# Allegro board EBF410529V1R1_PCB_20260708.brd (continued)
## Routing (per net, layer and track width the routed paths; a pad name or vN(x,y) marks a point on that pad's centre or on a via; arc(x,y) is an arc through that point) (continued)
USB3_OTG1_SSTXP: length 60.5
  TOP w0.135: J3.218 70.69,62.6 70.6,62.51 70.6,61.18 arc(70.63,61) 70.73,60.85 71.66,59.92 arc(71.82,59.81) 72.02,59.77 90.74,59.77 arc(91.65,59.95) 92.42,60.47 94.73,62.77 arc(94.84,62.95) 94.89,63.16 94.89,63.7 arc(95.03,64.4) 95.42,64.99 95.81,65.38 arc(96.68,65.96) 97.71,66.17 108.63,66.17 arc(108.81,66.2) 108.97,66.31 109.8,67.14 arc(109.91,67.3) 109.95,67.49 109.95,67.56 arc(109.92,67.72) 109.83,67.85 v1(109.69,67.99) ; v1(119.33,67.18) 119.19,67.32 arc(119.1,67.45) 119.07,67.61 119.07,67.75 arc(119.11,67.96) 119.23,68.15 C98.2
  ART03 w0.135: v1(109.69,67.99) 109.83,67.85 arc(109.92,67.72) 109.95,67.56 109.95,67.24 arc(110.41,66.14) 111.52,65.68 118.18,65.68 arc(118.81,65.94) 119.07,66.57 119.07,66.74 arc(119.1,66.9) 119.19,67.04 v1(119.33,67.18)
USB20_DM2: length 9.2
  TOP w0.135: J11.11 115.43,76.92 arc(115.35,76.73) 115.43,76.54 115.64,76.34 arc(115.75,76.17) 115.79,75.98 115.79,75.47 arc(115.85,75.12) 116.05,74.83 116.26,74.62 arc(116.38,74.57) 116.5,74.62 arc(116.62,74.67) 116.75,74.62 116.98,74.38 arc(117.03,74.26) 116.98,74.14 arc(116.93,74.02) 116.98,73.9 117.26,73.62 117.26,73.1 117.36,73 U15.9 U15.2 117.36,71.01 117.26,70.92 117.26,69.63 arc(117.29,69.47) R115.1
USB20_DP2: length 9.7
  TOP w0.135: R116.1 116.84,69.8 arc(116.88,69.85) 116.91,69.9 arc(116.94,69.99) 116.95,70.08 116.95,70.92 116.86,71.01 U15.1 U15.10 116.86,73 116.95,73.1 116.95,73.49 115.83,74.61 arc(115.57,75) 115.47,75.47 115.47,75.91 arc(115.45,76.04) 115.37,76.16 114.81,76.72 arc(114.3,77.06) J11.12
USB20_HOST_PWR_EN: length 103
  TOP w0.107: J3.224 72.19,66.19 71.12,67.26 71.12,72.86 v1(71.99,73.74) ; v1(138.81,85.79) 136.41,88.19 108.66,88.19 105.23,84.76 105.23,70.28 103,68.05 96.06,68.05 94.8,66.8 92.33,66.8 91.19,65.66 82.35,65.66 81.66,66.34 81.66,67.61 80.7,68.58 75.41,68.58 74.22,69.77 74.22,73.04 v1(73.52,73.74)
  BOTTOM w0.107: v1(71.99,73.74) v1(73.52,73.74) ; R134.1 v1(138.81,85.79)
USB30_DM: length 13.2
  BOTTOM w0.135: R105.1 116.8,69.76 arc(116.68,69.93) 116.64,70.13 116.64,70.37 arc(116.61,70.56) 116.5,70.71 116.35,70.87 116.35,71.17 116.44,71.27 U17.6 U17.5 116.44,73.26 116.35,73.35 116.35,73.8 116.53,73.99 arc(116.64,74.03) 116.74,73.99 arc(116.84,73.95) 116.94,73.99 117.12,74.17 arc(117.16,74.27) 117.12,74.37 arc(117.08,74.47) 117.12,74.57 117.3,74.75 arc(117.4,74.79) 117.5,74.75 arc(117.6,74.71) 117.7,74.75 117.88,74.93 arc(117.92,75.03) 117.88,75.13 117.85,75.16 arc(117.82,75.23) 117.85,75.3 117.92,75.37 117.92,75.84 arc(117.84,76.24) 117.61,76.58 117.15,77.04 117.15,77.25 116.04,78.37 arc(115.87,78.61) 115.81,78.91 115.81,80.09 arc(115.78,80.25) J11.2
USB30_DP: length 13.7
  BOTTOM w0.135: R106.1 116.17,69.81 arc(116.29,69.99) 116.33,70.19 116.33,70.37 arc(116.32,70.44) 116.28,70.49 116.04,70.74 116.04,71.17 115.94,71.27 U17.7 U17.4 115.94,73.26 116.04,73.35 116.04,73.93 117.61,75.5 117.61,75.84 arc(117.55,76.12) 117.39,76.36 116.84,76.91 116.84,77.12 115.81,78.15 arc(115.58,78.5) 115.5,78.91 115.5,78.93 arc(115.46,79.21) 115.35,79.48 arc(115.27,79.58) 115.19,79.68 114.6,80.27 arc(114.47,80.35) 114.33,80.38 J11.3
USB30_HOST_PWR_EN: length 81.3
  TOP w0.107: v1(73.52,72.74) 73.94,72.32 73.94,69.55 75.29,68.2 80.57,68.2 81.4,67.37 81.4,66.09 82.12,65.37 91.26,65.37 92.44,66.54 94.91,66.54 96.13,67.76 103.32,67.76 105.53,69.97 105.53,84.57 108.71,87.76 v1(119.49,87.76) ; v1(71.99,72.74) 71.53,72.27 71.53,67.46 72.69,66.3 J3.226
  BOTTOM w0.107: v1(71.99,72.74) v1(73.52,72.74) ; R121.1 v1(119.49,87.76)
USB30_RXN: length 12.8
  BOTTOM w0.135: J11.5 111.09,78.88 arc(111.25,78.85) 111.39,78.76 111.41,78.74 arc(111.5,78.6) 111.53,78.43 111.53,78.35 arc(111.58,78.12) 111.71,77.93 112.17,77.47 arc(112.28,77.19) 112.17,76.92 111.86,76.62 arc(111.65,76.3) 111.57,75.92 111.57,75.59 arc(111.66,75.15) 111.91,74.78 111.93,74.76 arc(112.3,74.51) 112.74,74.42 113.62,74.42 arc(113.83,74.38) 114,74.26 114.42,73.85 arc(114.51,73.72) 114.54,73.56 114.54,73.35 114.44,73.26 U17.1 U17.10 114.44,71.27 114.54,71.17 114.54,70.79 114.3,70.56 114.3,70.23 arc(114.28,70.08) 114.22,69.94 arc(114.17,69.85) 114.09,69.76 R110.1
USB30_RXP: length 12.7
  BOTTOM w0.135: R111.1 114.76,69.76 arc(114.65,69.93) 114.61,70.13 114.61,70.43 114.85,70.66 114.85,71.17 114.94,71.27 U17.9 U17.2 114.94,73.26 114.85,73.35 114.85,73.56 arc(114.79,73.83) 114.64,74.07 114.22,74.49 arc(113.95,74.67) 113.62,74.73 112.74,74.73 arc(112.42,74.8) 112.15,74.98 112.13,75 arc(111.95,75.27) 111.89,75.59 111.89,75.92 arc(111.94,76.18) 112.09,76.4 112.39,76.7 arc(112.59,77.19) 112.39,77.69 111.93,78.15 arc(111.87,78.24) 111.85,78.35 111.85,78.43 arc(111.88,78.6) 111.97,78.74 111.99,78.76 arc(112.13,78.85) 112.29,78.88 J11.6
USB30_TXN: length 11.2
  TOP w0.135: C97.1 118.65,69.58 arc(118.74,69.72) 118.77,69.88 118.77,70.09 118.61,70.25 arc(118.49,70.43) 118.45,70.63 118.45,70.92 118.36,71.01 U15.4 U15.7 118.36,73 118.45,73.1 118.45,73.39 arc(118.4,73.62) 118.27,73.82 117.95,74.14 arc(117.63,74.62) 117.52,75.18 117.52,75.72 arc(117.43,76.17) 117.18,76.55 117.13,76.59 arc(116.88,77.2) 117.13,77.82 117.4,78.08 arc(117.5,78.23) 117.53,78.4 117.53,78.43 arc(117.5,78.6) 117.41,78.74 117.39,78.76 arc(117.25,78.85) 117.09,78.88 J11.8
USB30_TXP: length 11.2
  TOP w0.135: J11.9 118.29,78.88 arc(118.13,78.85) 117.99,78.76 117.97,78.74 arc(117.88,78.6) 117.84,78.43 117.84,78.4 arc(117.79,78.11) 117.62,77.86 117.36,77.59 arc(117.19,77.2) 117.36,76.81 117.4,76.77 arc(117.72,76.29) 117.83,75.72 117.83,75.18 arc(117.92,74.74) 118.17,74.36 118.49,74.04 arc(118.69,73.74) 118.76,73.39 118.76,73.1 118.86,73 U15.6 U15.5 118.86,71.01 118.76,70.92 118.76,70.63 arc(118.78,70.55) 118.83,70.47 119.09,70.22 119.09,69.89 arc(119.13,69.68) 119.24,69.51 C98.1
USB_HUB_1V8: length 29.8
  TOP w0.254: U19.6 111.58,41.33 111.94,40.97 111.94,39.63 C126.1 v1(112.53,38.38) ; C124.1 v1(98.56,42.09) 99.31,42.83 U19.28 ; v1(102.23,50.6) C127.1 103.23,48.7 C123.1 103.25,48.31 104.08,47.48 U19.21 ; C125.1 v1(98.56,45.14) 99.37,44.33 U19.25
  ART03 w0.254: v1(98.56,45.14) 100.1,45.14 101.45,46.48 101.45,49.83 v1(102.23,50.6)
  BOTTOM w0.254: v1(98.56,45.14) 98.17,45.14 97.66,44.63 97.66,42.99 v1(98.56,42.09)
USB_HUB_3V3: length 63.1
  TOP w0.254: C110.1 v1(98.56,44.12) 98.85,43.83 U19.26 ; U19.43 105.58,36.14 C121.1 ; C116.1 v1(104.27,48.03) 104.58,47.71 U19.20 ; C121.1 C117.1 107.44,35.71 106.58,36.57 U19.45 ; C121.1 106.41,35.3 R130.2 105.41,33.45 105.08,33.13 103.91,33.13 103.38,33.66 R129.2 103.36,34.3 C120.1 102.36,35.31 102.11,35.56 102.11,38.48 101.77,38.82 101.09,38.82 U19.36 v1(100.08,38.83) ; U19.15 v1(107.08,44.83) ; U19.31 v1(102.05,41.33) ; R128.2 v1(114.24,45.14)
  TOP w0.381: C117.1 R127.2
  ART03 w0.254: v1(114.24,45.14) 114.24,47.13 112.88,48.49 109.75,48.49 108.76,47.5 108.76,45.21 108.38,44.83 v1(107.08,44.83)
  BOTTOM w0.254: 100.84,44.12 101.19,44.48 101.19,45.24 101.55,45.59 C118.1 ; 100.84,44.12 101.21,43.75 C109.1 ; 100.84,44.12 v1(98.56,44.12) ; C109.1 101.93,41.27 101.98,41.33 v1(102.05,41.33) ; C109.1 101.21,39.97 v1(100.08,38.83) ; C118.1 107.54,46.07 107.54,47.22 106.73,48.03 v1(104.27,48.03) ; C118.1 107.07,44.85 v1(107.08,44.83)
USB_HUB_3V3_OUT: length 5.1
  TOP w0.254: R128.1 C114.1 C115.1 112.26,42.83 U19.9
USB_HUB_5V0: length 5.1
  TOP w0.254: R126.2 C112.1 C113.1 112.29,42.33 U19.8
USB_HUB_DM1: length 32.6
  TOP w0.135: U19.18 105.58,46.63 105.49,46.72 105.49,47.81 arc(105.66,48.67) 106.16,49.41 107.26,50.52 arc(108.03,51.03) 108.95,51.22 113.35,51.22 arc(114.07,51.36) 114.68,51.77 117.32,54.41 arc(117.82,55.15) 117.99,56.02 117.99,64.26 arc(117.92,64.59) 117.74,64.87 116.6,66.01 arc(116.53,66.11) 116.51,66.23 116.51,66.29 arc(116.62,66.56) v1(116.88,66.67)
  BOTTOM w0.135: R105.2 116.78,68.4 arc(116.66,68.22) 116.62,68 116.62,67.88 arc(116.66,67.78) 116.75,67.74 116.75,67.74 arc(116.85,67.7) 116.89,67.6 116.89,67.34 arc(116.85,67.24) 116.75,67.2 116.75,67.2 arc(116.66,67.16) 116.62,67.06 116.62,66.8 arc(116.65,66.71) 116.75,66.67 v1(116.88,66.67)
USB_HUB_DM2: length 32.4
  TOP w0.135: U19.16 106.58,46.63 106.49,46.72 106.49,47.5 arc(106.63,48.18) 107.02,48.76 108.1,49.85 arc(108.62,50.2) 109.23,50.32 113.6,50.32 arc(114.63,50.52) 115.5,51.11 118.29,53.89 arc(118.87,54.76) 119.08,55.79 119.08,62.34 arc(119.11,62.42) 119.19,62.45 arc(119.27,62.49) 119.3,62.57 119.3,63.01 arc(119.27,63.09) 119.19,63.13 arc(119.11,63.16) 119.08,63.24 119.08,63.69 arc(119.11,63.77) 119.19,63.8 arc(119.27,63.83) 119.3,63.91 119.3,64.36 arc(119.27,64.44) 119.19,64.47 arc(119.11,64.51) 119.08,64.59 119.08,64.95 arc(118.96,65.52) 118.64,66 117.1,67.55 arc(117.04,67.63) 117.02,67.73 117.02,67.79 arc(117.05,67.95) 117.14,68.09 R115.2
USB_HUB_DM3: length 48.6
  TOP w0.135: U19.13 108.08,46.63 107.99,46.72 107.99,46.95 arc(108.01,47.02) 108.05,47.09 108.65,47.69 arc(109.03,47.94) 109.47,48.03 115.01,48.03 arc(115.9,48.21) 116.66,48.72 120.89,52.95 arc(121.21,53.42) 121.32,53.98 121.32,60.77 arc(121.5,61.68) 122.01,62.45 124.85,65.28 arc(125.62,65.8) 126.53,65.98 131.8,65.98 arc(132.15,66.05) 132.44,66.24 134.13,67.94 arc(134.33,68.23) 134.39,68.57 134.39,70.92 134.49,71.01 U18.2 U18.9 134.49,73 134.39,73.1 134.39,73.49 arc(134.35,73.73) 134.21,73.93 134.19,73.95 arc(134.06,74.15) 134.01,74.38 134.01,74.41 arc(134.06,74.64) 134.19,74.83 J12.2
USB_HUB_DM4: length 54.2
  TOP w0.135: U19.11 110.25,43.83 110.33,43.91 110.62,43.91 110.82,44.11 arc(110.95,44.31) 111,44.54 111,46.07 arc(111.04,46.29) 111.16,46.47 111.19,46.49 arc(111.37,46.62) 111.59,46.66 114.92,46.66 arc(115.95,46.86) 116.83,47.45 121.94,52.56 arc(122.38,53.22) 122.53,53.99 122.53,60.26 arc(122.67,60.97) 123.07,61.56 126.09,64.59 arc(126.28,64.72) 126.51,64.76 131.55,64.76 arc(132.58,64.97) 133.46,65.55 135.11,67.2 arc(135.69,68.07) 135.89,69.11 135.89,70.92 135.99,71.01 U18.5 U18.6 135.99,73 135.89,73.1 135.89,74.45 136.08,74.64 arc(136.21,74.83) 136.26,75.06 136.26,76.08 arc(136.19,76.43) 135.99,76.72 135.97,76.74 arc(135.68,76.94) 135.33,77.01 134.46,77.01 arc(134.29,77.04) 134.16,77.13 134.14,77.15 arc(134.04,77.29) 134.01,77.45 134.01,77.48 arc(134.02,77.55) 134.04,77.63 arc(134.07,77.69) 134.1,77.74 arc(134.12,77.76) 134.14,77.78 J12.8
USB_HUB_DM5: length 46.6
  TOP w0.135: U19.32 100.39,40.83 100.3,40.74 100.05,40.74 arc(99.4,40.47) 99.13,39.82 99.13,35.89 arc(99.23,35.37) 99.53,34.93 108.29,26.16 arc(109.09,25.63) 110.03,25.44 121.12,25.44 arc(121.46,25.51) 121.75,25.71 121.96,25.91 arc(122.15,26.04) 122.37,26.08 130.64,26.08 arc(130.86,26.04) 131.05,25.91 131.71,25.26 arc(131.83,25.07) 131.87,24.85 131.87,24.73 arc(131.83,24.51) 131.7,24.32 D33.1 131.77,23.87 arc(131.85,23.76) 131.87,23.63 131.87,23.6 arc(131.85,23.48) 131.77,23.37 R184.2
USB_HUB_DM6: length 23.7
  TOP w0.135: U19.34 101.88,39.83 101.97,39.74 103.91,39.74 arc(104.28,39.66) 104.59,39.46 104.7,39.35 arc(104.9,39.21) 105.13,39.17 106.86,39.17 arc(107.89,38.96) 108.76,38.38 109.86,37.28 arc(110.05,37.15) 110.27,37.11 114.21,37.11 arc(114.53,37.05) 114.8,36.87 115.42,36.25 arc(115.59,36.14) 115.78,36.1 122.41,36.1 arc(122.63,36.14) 122.81,36.26 122.85,36.3 arc(123.01,36.41) 123.21,36.45 R143.1
USB_HUB_DP1: length 32
  TOP w0.135: U19.19 105.08,46.63 105.18,46.72 105.18,47.81 arc(105.37,48.79) 105.93,49.63 107.04,50.74 arc(107.91,51.32) 108.95,51.53 113.35,51.53 arc(113.95,51.65) 114.46,51.99 117.1,54.63 arc(117.53,55.27) 117.68,56.02 117.68,64.26 arc(117.64,64.47) 117.52,64.65 116.38,65.79 arc(116.24,65.99) 116.19,66.23 116.19,66.42 arc(116.18,66.5) 116.13,66.58 v1(116.04,66.67)
  BOTTOM w0.135: v1(116.04,66.67) 116.18,66.81 arc(116.27,66.94) 116.3,67.1 116.3,68.07 arc(116.27,68.22) 116.19,68.35 R106.2
USB_HUB_DP2: length 31.9
  TOP w0.135: R116.2 116.55,68.16 arc(116.67,67.98) 116.71,67.77 116.71,67.73 arc(116.75,67.51) 116.88,67.32 118.42,65.78 arc(118.67,65.4) 118.76,64.95 118.76,55.79 arc(118.58,54.88) 118.07,54.11 115.28,51.33 arc(114.51,50.81) 113.6,50.63 109.23,50.63 arc(108.5,50.49) 107.88,50.07 106.79,48.98 arc(106.34,48.3) 106.18,47.5 106.18,46.72 106.08,46.63 U19.17
USB_HUB_DP3: length 48.6
  TOP w0.135: J12.3 133.58,74.77 arc(133.67,74.64) 133.7,74.49 133.7,74.26 arc(133.75,74.02) 133.88,73.82 133.91,73.79 arc(134.04,73.6) 134.08,73.37 134.08,73.1 133.99,73 U18.10 U18.1 133.99,71.01 134.08,70.92 134.08,68.57 arc(134.04,68.35) 133.91,68.16 132.22,66.46 arc(132.03,66.34) 131.8,66.29 126.53,66.29 arc(125.5,66.09) 124.63,65.51 121.79,62.67 arc(121.21,61.8) 121.01,60.77 121.01,53.98 arc(120.92,53.54) 120.67,53.17 116.44,48.94 arc(115.78,48.5) 115.01,48.34 109.47,48.34 arc(108.91,48.23) 108.43,47.91 107.83,47.31 arc(107.72,47.14) 107.68,46.95 107.68,46.72 107.58,46.63 U19.14
USB_HUB_DP4: length 54.2
  TOP w0.135: J12.9 133.05,78.5 arc(133.42,78.39) 133.66,78.1 arc(133.69,78) 133.7,77.9 133.7,77.39 arc(133.74,77.16) 133.87,76.97 133.93,76.91 arc(134.17,76.75) 134.46,76.69 135.33,76.69 arc(135.56,76.65) 135.75,76.52 135.77,76.5 arc(135.9,76.31) 135.95,76.08 135.95,75.06 arc(135.92,74.95) 135.86,74.86 135.58,74.58 135.58,74.32 arc(135.55,74.24) 135.47,74.2 arc(135.39,74.17) 135.36,74.09 135.36,73.78 arc(135.39,73.7) 135.47,73.67 arc(135.55,73.63) 135.58,73.55 135.58,73.1 135.49,73 U18.7 U18.4 135.49,71.01 135.58,70.92 135.58,69.11 arc(135.4,68.19) 134.88,67.42 133.23,65.77 arc(132.46,65.26) 131.55,65.07 126.51,65.07 arc(126.16,65.01) 125.87,64.81 122.85,61.79 arc(122.38,61.09) 122.22,60.26 122.22,53.99 arc(122.09,53.34) 121.72,52.78 116.6,47.67 arc(115.83,47.15) 114.92,46.97 111.59,46.97 arc(111.25,46.91) 110.97,46.71 110.94,46.69 arc(110.75,46.41) 110.69,46.07 110.69,44.54 arc(110.66,44.43) 110.6,44.33 110.49,44.22 110.4,44.22 arc(110.34,44.23) 110.29,44.27 110.27,44.29 arc(110.22,44.32) 110.17,44.33 U19.12
USB_HUB_DP5: length 46.7
  TOP w0.135: R185.2 132.28,23.37 arc(132.21,23.48) 132.19,23.6 132.19,23.63 arc(132.21,23.76) 132.28,23.87 D32.1 132.36,24.32 arc(132.23,24.51) 132.19,24.73 132.19,24.85 arc(132.12,25.19) 131.93,25.48 131.27,26.13 arc(130.98,26.32) 130.64,26.39 122.37,26.39 arc(122.03,26.32) 121.74,26.13 121.53,25.93 arc(121.34,25.8) 121.12,25.76 110.03,25.76 arc(109.21,25.92) 108.51,26.38 99.75,35.15 arc(99.52,35.49) 99.44,35.89 99.44,36.46 arc(99.48,36.55) 99.57,36.59 arc(99.66,36.62) 99.69,36.71 99.69,37 arc(99.66,37.09) 99.57,37.12 arc(99.48,37.16) 99.44,37.25 99.44,37.54 arc(99.48,37.62) 99.57,37.66 arc(99.66,37.7) 99.69,37.79 99.69,38.07 arc(99.66,38.16) 99.57,38.2 arc(99.48,38.24) 99.44,38.33 99.44,39.82 arc(99.62,40.25) 100.05,40.42 100.29,40.42 100.39,40.33 U19.33
USB_HUB_DP6: length 23.7
  TOP w0.135: R138.1 123.21,35.43 arc(123.01,35.47) 122.85,35.58 122.81,35.62 arc(122.63,35.74) 122.41,35.78 115.78,35.78 arc(115.47,35.85) 115.2,36.03 114.58,36.65 arc(114.41,36.76) 114.21,36.8 110.27,36.8 arc(109.93,36.87) 109.64,37.06 108.54,38.16 arc(107.77,38.67) 106.86,38.85 105.13,38.85 arc(104.78,38.92) 104.48,39.12 104.36,39.24 arc(104.16,39.38) 103.91,39.42 101.97,39.42 101.88,39.33 U19.35
WIFI_PWR_EN: length 95.3
  TOP w0.107: R155.1 115.24,39.93 115.24,41.55 v1(115.67,41.99) ; J3.170 58.69,62.44 v1(58.69,62.44)
  BOTTOM w0.107: v1(58.69,62.44) 58.6,62.44 57.76,61.59 57.76,36.73 60.84,33.65 70.05,33.65 70.89,34.49 75.56,34.49 76.12,33.93 77.95,33.93 78.25,33.64 86.29,33.64 87.1,34.44 105.82,34.44 109.88,38.51 109.88,40.31 111.15,41.58 114.94,41.58 115.34,41.99 v1(115.67,41.99)
N16958730: length 10.8
  BOTTOM w0.6: J1.1 10.68,88.09 14.33,88.09 L2.1 J1.5
N16959452: length 3.4
  TOP w0.203: R3.2 8.68,66.67 8.89,66.46 v1(8.89,65.28)
  BOTTOM w0.203: U1.5 v1(8.89,65.28)
N16959497: length 1.3
  BOTTOM w0.381: U1.6 7.86,64.13 C1.1
N16959529: length 3.9
  BOTTOM w0.254: R1.1 C2.1 R2.1 U1.4
N16961195: length 4
  BOTTOM w0.254: C11.1 R6.1 R7.1 16.38,66.23 U2.4
N16961199: length 1.3
  BOTTOM w0.381: C10.1 15.42,63.32 U2.6
N16961300: length 3.8
  BOTTOM w0.381: R9.1 R8.1 14.34,66.02 15.09,65.28 U2.5
N16963036: length 1.5
  TOP w0.107: LED1.2 v1(136.25,2.26)
  BOTTOM w0.107: v1(136.25,2.26) 136.27,2.29 R4.2
N16963423: length 1.5
  TOP w0.107: LED2.2 v1(140.06,2.26)
  BOTTOM w0.107: v1(140.06,2.26) 140.08,2.29 R12.2
N16965184: length 5.6
  BOTTOM w0.132: J4.1 132.68,15.21 D8.2 131.94,14.48 130.55,14.48 R17.2
N16965201: length 5.5
  BOTTOM w0.132: R18.2 130.43,15.74 132.06,15.74 D7.2 132.63,16.31 J4.2
N16965205: length 5.6
  BOTTOM w0.132: J4.3 132.59,17.41 D6.2 131.97,16.79 130.52,16.79 R19.2
N16965209: length 6.6
  BOTTOM w0.132: R20.2 129.91,20.31 130.23,20.63 132.28,20.63 132.58,20.33 D5.2 132.66,19.61 J4.5
N16965213: length 5.5
  BOTTOM w0.132: J4.7 132.67,21.81 D4.2 132.06,21.2 130.43,21.2 R23.2
N16965217: length 5.5
  BOTTOM w0.132: J4.8 132.63,22.91 D3.2 132.06,22.34 130.43,22.34 R24.2
N16965221: length 5.5
  BOTTOM w0.132: R25.2 130.58,24 131.09,23.48 132.06,23.48 D2.2 134.98,24 J4.9
N16966392: length 1.9
  TOP w0.107: U4.3 139.48,7.09 R26.2
N16966399: length 4.2
  TOP w0.107: U4.2 138.21,7.09 C23.1 138.17,7.11 C22.1 R22.2
N16970771: length 4.9
  TOP w0.132: R39.2 63.15,25.1 63.88,25.1 65.17,26.38 U7.23
N16970773: length 4.4
  TOP w0.132: R36.2 63.79,24.71 64.14,24.71 65.57,26.15 U7.24
N16970775: length 4
  TOP w0.132: U7.25 65.97,25.88 R37.2
N16970777: length 3.7
  TOP w0.132: U7.26 66.37,25.26 R42.2
N16970779: length 3.4
  TOP w0.132: R41.2 66.77,24.65 U7.27
N16970781: length 5.4
  TOP w0.132: U7.22 64.77,26.62 63.63,25.48 62.52,25.48 R40.2
N16970797: length 4.4
  TOP w0.132: R49.2 70.71,29.03 70.02,29.72 U7.35
N16970858: length 6.4
  TOP w0.203: U7.36 69.93,30.12 C42.1 71.38,31.57 73.02,31.57 74.03,30.56 Y2.3
N16970862: length 5.2
  TOP w0.203: Y2.1 72.53,32.73 71.76,31.96 C41.1 70.19,31.41 70.19,30.93 69.78,30.52 U7.37
N16970890: length 7.5
  TOP w0.107: D59.2 62.74,36.27 62.74,34.93 R158.2 ; R158.2 62.22,34.42 C45.1 63.02,32.61 63.02,31.52 63.22,31.32 U7.12 ; R158.2 R53.2
N16971097: length 3.4
  TOP w0.203: R38.1 69.6,33.73 69.6,31.75 69.17,31.32 U7.39
N16971238: length 3
  BOTTOM w0.508: J6.1 68.45,69.21 C43.1
N16971259: length 117.9
  TOP w1.016: J6.15 J6.16 54.98,76.79 J6.10
  GND02 w1.016: J6.10 54.98,76.79 J6.16 J6.15
  ART03 w1.016: J6.15 J6.16 54.98,76.79 J6.10
  PWR04 w1.016: J6.15 J6.16 54.98,76.79 J6.10
  GND05 w1.016: J6.10 54.98,76.79 J6.16 J6.15
  BOTTOM w1.016: J6.15 63.92,78.05 R55.1 63.67,78.05 C44.1 J6.16 54.98,76.79 J6.10
N16971318: length 3.7
  BOTTOM w0.107: J6.12 63.13,86 R50.1
N16971320: length 3.5
  BOTTOM w0.107: R51.1 62.09,86 J6.13
N16971466: length 2.2
  TOP w0.203: U7.32 69.46,28.52 v1(69.96,28.02)
  BOTTOM w0.203: v1(69.96,28.02) R52.1
N16971541: length 5.5
  TOP w0.203: R46.2 72.34,25 69.21,28.12 U7.31
N16976499: length 3.7
  TOP w0.132: U8.26 82.6,25.26 R68.2
N16976501: length 4
  TOP w0.132: U8.25 82.2,25.88 R60.2
N16976503: length 4.4
  TOP w0.132: R61.2 80.02,24.71 80.37,24.71 81.8,26.15 U8.24
N16976505: length 4.9
  TOP w0.132: R63.2 79.38,25.1 80.11,25.1 81.4,26.38 U8.23
N16976507: length 5.4
  TOP w0.132: U8.22 81,26.64 79.83,25.48 78.75,25.48 R64.2
N16976509: length 3.4
  TOP w0.132: U8.27 83,24.65 R67.2
N16976515: length 4.4
  TOP w0.132: U8.35 86.27,29.72 86.96,29.03 R73.2
N16976541: length 5.2
  TOP w0.203: U8.37 86.01,30.52 86.42,30.93 86.42,31.41 C57.1 87.99,31.96 88.76,32.73 Y3.1
N16976545: length 6.4
  TOP w0.203: Y3.3 90.26,30.56 89.25,31.57 87.61,31.57 C58.1 86.16,30.12 U8.36
N16976569: length 6.2
  TOP w0.107: D60.2 78.69,35.64 R159.2 R77.2 C61.1 79.27,32.61 79.27,31.47 79.42,31.32 U8.12
N16976627: length 3.7
  TOP w0.203: R62.1 86.08,33.47 86.08,31.96 85.44,31.32 U8.39
N16976697: length 2.2
  TOP w0.203: U8.32 85.69,28.52 v1(86.19,28.02)
  BOTTOM w0.203: v1(86.19,28.02) R76.1
N16976807: length 3.3
  BOTTOM w0.508: C59.1 J7.1
N16976809: length 117.9
  TOP w1.016: J7.15 J7.16 74.51,76.79 J7.10
  GND02 w1.016: J7.10 74.51,76.79 J7.16 J7.15
  ART03 w1.016: J7.15 J7.16 74.51,76.79 J7.10
  PWR04 w1.016: J7.15 J7.16 74.51,76.79 J7.10
  GND05 w1.016: J7.10 74.51,76.79 J7.16 J7.15
  BOTTOM w1.016: J7.15 83.48,78.05 R78.1 81.19,77.92 C60.1 J7.16 74.51,76.79 J7.10
N16976831: length 3.5
  BOTTOM w0.107: J7.13 81.65,86 R75.1
N16976833: length 3.7
  BOTTOM w0.107: R74.1 82.69,86 J7.12
N16976861: length 5.5
  TOP w0.203: U8.31 85.44,28.12 88.57,25 R70.2
N16985416: length 20.4
  PWR04 w0.762: J10.2 J10.1
  BOTTOM w0.762: L11.1 32.34,88.38 J10.2 31.58,88.98 24.29,88.98 J10.3 J10.4
N16990092: length 1.4
  BOTTOM w0.254: R120.1 30.25,80.4 U12.3
N16998300: length 4.7
  BOTTOM w0.107: Q10.2 81.13,63.94 R152.2 R150.2
N17003573: length 20
  TOP w0.107: R165.1 R164.2 100.7,53.9 Q21.1 100.7,56.07 100.91,56.29 102.58,56.29 102.79,56.5 102.79,58.1 102.58,58.32 101.02,58.32 100.7,58.64 Q19.1 101.37,60.43 103.71,60.43 Q18.1 105.05,60.43 106.86,60.43 107.53,59.75 Q20.1
N17013167: length 6.1
  TOP w0.107: R142.2 108.13,55.24 Q8.1 108.06,57.13 107.85,57.34 Q9.3
N17014356: length 17.9
  TOP w0.107: v1(102.51,61.34) 103.02,60.83 107.09,60.83 107.39,60.53 108.56,60.53 108.81,60.27 108.81,59.16 108.25,58.6 104.7,58.6 104.38,58.28 Q9.1 104.38,53.9 R151.1
  BOTTOM w0.107: v1(102.51,61.34) 102.11,61.75 R149.1
N17029455: length 11.2
  BOTTOM w0.203: R153.2 C148.1 118.62,18.41 118.34,18.14 U24.4 119.66,17.48 120.07,17.88 120.07,19.15 120.47,19.56 123.14,19.56 123.55,19.15 U25.4
N17029502: length 1.6
  BOTTOM w0.203: R154.1 115.84,18.67 U24.3
N17029521: length 2.1
  BOTTOM w0.203: U25.3 121.05,18.73 121.26,18.94 R161.1
N17036087: length 7.7
  BOTTOM w0.132: R173.2 129.86,33.96 131.23,33.96 C169.1 131.87,34.59 U27.6 133.23,35.82 134.04,36.63 J19.2
N17036090: length 7.4
  BOTTOM w0.132: J19.3 133.4,39.17 132.72,38.48 132.72,37.04 132.49,36.82 U27.4 131.87,38.07 C168.1 R174.2
N17036093: length 10.4
  BOTTOM w0.132: J19.7 133.49,37.9 133.22,37.64 133.22,36.54 133.01,36.32 U27.5 131.44,36.32 131.32,36.45 131.32,37.21 131.13,37.4 129.85,37.4 R171.2 C167.1 R175.2
N17043505: length 1.6
  TOP w0.381: C161.1 U26.6
N17043507: length 3.6
  TOP w0.203: U26.4 v1(112.97,27)
  BOTTOM w0.254: v1(112.97,27) R176.1 112.98,27.82 C164.1 R172.1
N17043614: length 2.6
  TOP w0.203: U26.5 v1(113.92,27)
  BOTTOM w0.254: R177.2 114.05,28.82 R178.1 114.05,27.13 v1(113.92,27)
N17043933: length 10
  TOP w0.107: J20.1 114.42,11.69 111.64,14.47 R180.2 R179.2
N17044212: length 10.6
  TOP w0.132: J20.7 116.82,9.38 116.46,9.02 110.49,9.02 109.09,10.41 108.09,10.41 R181.2
N17046085: length 3.6
  TOP w0.135: R185.1 132.35,21.91 arc(132.23,21.72) 132.18,21.5 132.18,20.55 132.18,20.27 arc(132.2,20.15) 132.27,20.05 132.31,20.01 arc(132.4,19.88) 132.42,19.74 J20.38
N17046088: length 3.6
  TOP w0.135: R184.1 131.7,21.92 arc(131.82,21.73) 131.87,21.51 131.87,20.55 131.87,20.42 131.87,20.27 arc(131.84,20.15) 131.78,20.05 131.74,20.01 arc(131.65,19.88) 131.62,19.74 J20.36
N17046548: length 3.5
  TOP w0.107: J20.20 125.22,21.98 R182.1
N17046561: length 3.7
  TOP w0.107: J20.22 126.02,19.95 125.7,20.27 125.7,21.7 R183.1
N17063858: length 1.7
  BOTTOM w0.203: U9.16 27.86,61.89 C68.1
N17063899: length 5.4
  BOTTOM w0.2: U9.2 24.26,55.75 23.11,55.75 C72.1 C73.1 L9.2
N17064255: length 2.6
  BOTTOM w0.203: U9.24 28.43,58.34 29.57,57.2 30.1,57.2 C71.1
N17064258: length 2.3
  BOTTOM w0.203: U9.23 28.72,58.62 29.74,57.6 30.1,57.6 C74.1
N17064495: length 1.6
  BOTTOM w0.203: C75.1 30.1,59.23 29.3,59.23 U9.22
N17064497: length 1.6
  BOTTOM w0.203: C76.1 30.1,59.64 29.3,59.64 U9.21
N17064707: length 2
  BOTTOM w0.2: C78.1 29.47,60.96 U9.20
N17064710: length 2.6
  BOTTOM w0.2: U9.19 28.41,60.53 29.85,61.97 C79.1
N17064713: length 2.9
  BOTTOM w0.107: U9.10 24.21,61.26 24.21,62.55 C80.1
N17064960: length 2.1
  BOTTOM w0.2: U9.26 28.09,57.37 28.09,57.2 28.53,56.77 R91.2
N17065329: length 2.1
  BOTTOM w0.254: C85.1 R97.1 R99.1
N17072089: length 13.3
  TOP w0.203: R83.1 45.03,85.69 45.03,84.28 45.69,83.62 45.69,80.34 45.29,79.93 C65.1 44.44,78.92 R81.1 ; R83.1 R84.2 ; R83.1 D14.2 J8.1
N17072509: length 3.8
  TOP w0.203: R84.1 R82.1 42.88,83.7 42.88,82.51 C70.1
N17073944: length 2
  BOTTOM w0.203: R92.1 46.8,84.25 J8.2
N17074279: length 9.8
  BOTTOM w0.203: R88.1 R87.2 C83.1 43.84,86.22 D15.2 45.05,86.03 51.38,86.03 J8.6
N17074336: length 14.6
  TOP w0.203: v1(45.63,72.71) Q5.2
  BOTTOM w0.203: J8.3 46.85,80.91 48.92,78.84 48.92,78.21 48.72,78 47.8,78 47.32,77.52 47.32,76.79 D17.2 47.29,76.14 47.29,75.75 R243.1 47.35,75.07 47.35,74.27 45.78,72.71 v1(45.63,72.71)
N17074726: length 18.7
  TOP w0.203: Q4.2 45.49,68.26 v1(45.63,68.4)
  BOTTOM w0.203: J8.4 49.29,78.83 49.29,78.07 48.82,77.6 47.92,77.6 47.68,77.35 47.68,76.79 D16.2 47.65,76.09 47.65,75.8 R242.1 47.7,75.13 47.7,74.12 45.63,72.05 v1(45.63,68.4)
N17074747: length 2.3
  TOP w0.203: Q4.3 45.13,69.22 R90.1 47.37,69.22 R89.1
N17075125: length 1.5
  TOP w0.203: R89.2 C81.1
N17075408: length 2.3
  TOP w0.203: R93.1 46.36,73.66 R94.1 45.13,73.65 Q5.3
N17075443: length 1.5
  TOP w0.203: R93.2 C82.1
N17075521: length 10.3
  TOP w0.107: Q5.1 43.09,73.93 42.42,73.25 42.42,70.84 Q4.1 44.42,71.5 C84.1 45.86,70.99 46.87,70.99 R95.1
N17112236: length 5.6
  BOTTOM w0.203: Y1.2 5.09,47.98 C29.1 2.87,51.49 U5.2
N17112246: length 4.5
  BOTTOM w0.203: Y1.1 4.06,47.98 C28.1 3.73,49.6 3.73,49.89 2.78,50.84 U5.1
N17117541: length 1.4
  BOTTOM w0.254: R118.2 32.75,80.29 U12.4
N17135429: length 2.1
  TOP w0.254: U3.3 10.86,42.81 11.3,42.37 11.88,42.37 R5.1
N17149641: length 1.7
  BOTTOM w0.305: U13.4 117.53,87.69 R121.2
N17149662: length 1.8
  BOTTOM w0.305: U13.3 111.68,87.69 R125.1
N17150434: length 28.9
  ART03 w0.762: J11.22 J11.19
  BOTTOM w0.762: J11.22 J11.21 ; L10.1 108.06,82.43 J11.19 J11.20
N17156781: length 3.3
  TOP w0.107: R133.1 98.68,43.1 98.91,43.33 U19.27
N17157129: length 9.2
  TOP w0.203: Y4.3 97.04,49.21 97.99,48.26 99.76,48.26 C131.1 100.59,48.31 101.32,48.31 101.93,47.7 103,47.7 103.58,47.11 U19.22
N17157136: length 6.9
  TOP w0.203: Y4.1 98.54,47.23 99.2,47.89 99.98,47.89 C130.1 100.49,47.96 101.17,47.96 101.78,47.35 102.85,47.35 103.08,47.11 U19.23
N17158781: length 3.1
  TOP w0.254: R130.1 C122.1 104.39,36.07 104.58,36.26 U19.41
N17159812: length 2.3
  TOP w0.254: U19.40 104.08,36.52 103.38,35.81 R129.1
N17161099: length 4.2
  TOP w0.135: R131.2 98.09,40.24 arc(98.28,40.36) 98.5,40.41 98.52,40.41 arc(98.94,40.58) 99.11,41 99.11,41.15 arc(99.14,41.31) 99.24,41.45 99.55,41.77 arc(99.73,41.88) 99.94,41.92 100.19,41.92 100.29,41.83 U19.30
N17161102: length 4.2
  TOP w0.135: R132.2 98.09,40.89 arc(98.28,40.76) 98.5,40.72 98.52,40.72 arc(98.72,40.8) 98.8,41 98.8,41.15 arc(98.85,41.43) 99.02,41.67 99.33,41.99 arc(99.61,42.17) 99.94,42.24 100.19,42.24 100.29,42.33 U19.29
N17163205: length 30.1
  TOP w0.762: J12.11 J12.12
  BOTTOM w0.762: J12.12 J12.6 ; J12.5 J12.11 L12.1
N17166688: length 4
  BOTTOM w0.254: R134.2 C132.1 U20.4
N17166697: length 2.1
  BOTTOM w0.254: U20.3 R135.1
N17204481: length 4.6
  TOP w0.107: J21.2 2.67,77.95 D34.2 R187.1
N17204515: length 4.3
  TOP w0.107: R186.1 D35.2 7.75,77.55 6.86,78.44 J21.1
N17208013: length 2.2
  TOP w0.381: R11.1 99.52,19.3 Q1.3
N17208331: length 6.1
  TOP w0.381: R11.2 D1.1 99.42,15.34 J2.1
N17208813: length 5.7
  TOP w0.107: Q2.3 104.36,17.06 104.06,16.76 R10.2 103.63,17.81 103.09,18.35 Q1.1
N17208925: length 3
  TOP w0.107: Q2.1 106.39,16.79 R14.1 R13.2
N17240897: length 13
  TOP w0.203: R192.2 C180.2 70.98,15.32 Q17.3 71.92,17 72.13,17.21 Q16.1 74.78,17.21 75.18,16.8 75.18,14.19 74.78,13.78 Q15.1
N17241660: length 5.9
  TOP w0.107: Q17.1 69.03,17.21 R194.1 67.95,16.12 67.95,13.32 R193.2
N17241919: length 3
  TOP w0.254: R195.2 C184.1 59.08,16.88 U31.4
N17241951: length 2.9
  TOP w0.254: U31.3 62.23,15.3 62.48,15.56 62.48,16.5 R196.1
N17242291: length 4.2
  TOP w0.254: R200.2 62.62,18.16 C188.1 63.9,16.88 U32.4
N17242323: length 2
  TOP w0.254: R197.1 66.4,16.88 U32.3
N17257942: length 2
  TOP w0.107: R199.2 11.27,44.84 10.86,45.25 U3.4
N17272255: length 5
  TOP w0.381: U33.16 55.07,20.82 54.49,20.24 v1(54.49,19.19)
  BOTTOM w0.381: L15.1 C191.1 54.36,19.19 v1(54.49,19.19)
N17272410: length 3.1
  TOP w0.254: U33.3 v1(52.18,18.28)
  BOTTOM w0.254: v1(52.18,18.28) 51.52,18.94 C192.1
N17272413: length 2.1
  TOP w0.254: U33.1 v1(52.18,20.82)
  BOTTOM w0.254: v1(52.18,20.82) 52.05,20.69 C192.2
N17272453: length 2.1
  TOP w0.254: U33.4 v1(52.18,17.02)
  BOTTOM w0.254: v1(52.18,17.02) 52.05,16.89 C193.2
N17272456: length 2.1
  TOP w0.254: U33.5 v1(52.18,15.74)
  BOTTOM w0.254: v1(52.18,15.74) 52.03,15.89 C193.1
N17272490: length 2.2
  TOP w0.254: U33.6 v1(52.18,14.48)
  BOTTOM w0.254: v1(52.18,14.48) 51.92,14.48 C194.1
N17272493: length 2.8
  TOP w0.254: U33.2 v1(52.18,19.56)
  BOTTOM w0.254: v1(52.18,19.56) 52.18,20.04 C195.1
N17276502: length 16.3
  TOP w0.107: R207.2 85.19,15.35 85.19,12.57 D29.2 85.85,9.14 86.66,8.33 88.44,8.33 91.72,5.05 J30.2
N17276503: length 16.2
  TOP w0.107: R208.2 83.41,15.35 83.41,12.57 D28.2 84.07,8.99 85.8,7.26 87.58,7.26 89.72,5.12 J30.3
N17276504: length 16
  TOP w0.107: R209.2 81.64,15.35 81.64,12.57 D27.2 82.3,8.81 85.14,5.97 86.77,5.97 87.72,5.02 J30.4
N17276505: length 15
  TOP w0.107: J30.5 80.52,8.91 D26.2 79.86,12.57 79.86,15.35 R210.2
N17284003: length 2
  TOP w0.254: R213.2 D41.1
N17284390: length 2
  TOP w0.254: R215.2 D42.1
N17313600: length 1.5
  TOP w0.381: C204.1 29.58,68.96 U38.6
N17313897: length 1.9
  TOP w0.381: U38.4 R96.2
N17313900: length 1.9
  TOP w0.381: U38.3 R98.2
N17314015: length 2.3
  TOP w0.381: R98.1 19.3,68.96 18.91,69.34 C87.2
N17314022: length 1.3
  TOP w0.381: R96.1 C86.2
N17314158: length 6
  TOP w0.107: U38.1 R100.1 21.2,72.35 20.99,72.57 19.13,72.57 18.91,72.35 R102.2
N17314600: length 1.9
  TOP w0.381: U38.2 C88.1
N17314610: length 1.7
  TOP w0.381: U38.5 L18.1
N17314613: length 1.7
  TOP w0.381: U38.8 L19.1
N17315365: length 1.5
  BOTTOM w0.381: C210.1 29.58,70.23 U10.6
N17315397: length 1.9
  BOTTOM w0.381: U10.3 R224.2
N17315399: length 1.9
  BOTTOM w0.381: U10.4 R223.2
N17315425: length 1.3
  BOTTOM w0.381: R224.1 C212.2
N17315432: length 1.3
  BOTTOM w0.381: R223.1 C211.2
N17315446: length 4.6
  BOTTOM w0.107: U10.1 R226.1 20.67,67.16 19.71,67.16 19.18,67.69 R225.2
N17315502: length 1.9
  BOTTOM w0.381: U10.2 C215.1
N17315506: length 1.7
  BOTTOM w0.381: U10.8 L21.1
N17315508: length 1.7
  BOTTOM w0.381: U10.5 L20.1
N17318769: length 35.4
  ART03 w0.762: J33.G3 J33.G4 101.07,84.63 100.31,85.39 95.33,85.39 94.57,84.63 J33.G2 J33.G1
  BOTTOM w0.762: J33.G4 99.81,82.21 L27.2
N17319613: length 11.1
  TOP w0.107: v1(99.57,63.77) v1(100.97,63.77) 100.97,61.93 99.97,60.93 99.97,57.55 100.19,57.34 Q21.3
  BOTTOM w0.107: R233.2 v1(100.97,63.77) ; R234.2 v1(99.57,63.77)
N17319615: length 4.9
  TOP w0.107: Q20.3 109.02,63.34 v1(108.58,63.77) 108.58,63.78 107.2,63.78 v1(107.19,63.77)
  BOTTOM w0.107: R232.2 v1(108.58,63.77) ; R231.2 v1(107.19,63.77)
N17319817: length 8.3
  TOP w0.107: v1(97.03,63.78) v1(98.42,63.78) 98.83,64.19 101.22,64.19 101.65,63.75 Q19.3
  BOTTOM w0.107: R230.2 v1(97.03,63.78) ; R229.2 v1(98.42,63.78)
N17319825: length 5
  TOP w0.107: Q18.3 105.33,62.64 106.05,63.35 v1(106.05,63.77) v1(104.65,63.77)
  BOTTOM w0.107: R228.2 v1(106.05,63.77) ; R227.2 v1(104.65,63.77)
N17366542: length 8.5
  TOP w0.559: C140.1 147.07,32.89 C136.1 U22.2
N17366552: length 2.8
  TOP w0.559: C140.2 147.07,35.04 C137.1 147.07,36.67 CN1.1
N17367118: length 5
  TOP w0.135: U22.6 127.05,33.93 arc(127.02,34.1) 126.92,34.24 126.91,34.26 arc(126.77,34.35) 126.6,34.38 126.05,34.38 arc(125.77,34.44) 125.53,34.6 125.51,34.62 arc(125.35,34.86) 125.29,35.14 125.29,35.34 arc(125.26,35.5) 125.17,35.64 125.09,35.72 arc(125.01,35.77) 124.93,35.78 124.9,35.78 arc(124.81,35.77) 124.74,35.72 R138.2
N17367190: length 5
  TOP w0.135: R143.2 124.69,36.21 arc(124.82,36.13) 124.96,36.1 124.99,36.1 arc(125.14,36.07) 125.26,35.98 125.39,35.86 arc(125.55,35.62) 125.6,35.34 125.6,35.14 arc(125.64,34.98) 125.73,34.84 125.75,34.82 arc(125.89,34.73) 126.05,34.69 126.6,34.69 arc(126.77,34.73) 126.91,34.82 126.92,34.84 arc(127.02,34.98) 127.05,35.14 U22.7
N17367932: length 4
  TOP w0.107: R155.2 R148.2 C143.2 118.56,40.54 Q11.1
N17525748: length 2.9
  BOTTOM w0.107: Q3.3 14.23,50.04 R241.2 15.46,49.54 Q12.1

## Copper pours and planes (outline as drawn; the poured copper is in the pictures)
3V3_OUT on TOP: 60.96,12.78 60.96,13.72 62.18,13.72 62.26,13.64 62.26,12.45 62.15,12.34 61.37,12.34 61.14,12.12 61.14,11.51 61.09,11.46 59.56,11.46 59.54,11.48 59.54,12.06 60.25,12.06
5V_OUT on TOP: 64.31,11.51 64.31,12.09 64.89,12.09 65.79,12.98 65.79,13.72 66.97,13.72 66.97,12.47 66.83,12.32 66.14,12.32 65.96,12.14 65.96,11.51 65.91,11.46 64.36,11.46
12V on TOP: 75.39,11.68 75.46,11.5 75.64,11.43 77.06,11.43 77.24,11.5 77.32,11.68 77.32,13.59 77.24,13.77 77.06,13.84 75.64,13.84 75.46,13.77 75.39,13.59
12V on TOP: 6.6,69.67 6.35,69.42 6.35,68.15 6.6,67.89 11.71,67.89 12.04,67.56 14.15,67.56 14.48,67.89 14.48,69.34 14.15,69.67
12V on TOP: 111.81,30.05 112.17,29.69 113.31,29.69 113.36,29.74 113.36,31.17 113.72,31.52 113.72,34.8 113.56,34.95 111.94,34.95 111.81,34.82
12V on TOP: 40.6,68.72 40.6,67.45 40.73,67.32 41.92,67.32 42.05,67.45 42.05,68.75 41.92,68.87 40.75,68.87
12V on BOTTOM: 41.88,67.61 41.88,68.88 40.79,68.88 40.64,68.73 40.64,67.67 40.82,67.49 41.76,67.49
12V on BOTTOM: 5.16,65.94 5.16,69.09 5.59,69.52 10.44,69.52 10.67,69.75 10.67,71.22 11.51,72.06 11.51,75.08 11.86,75.44 15.47,75.44 15.72,75.18 15.72,72.42 15.44,72.14 14.27,72.14 13.87,71.73 13.87,69.98 14.48,69.37 14.48,68.07 14.3,67.89 13.89,67.89 13.74,67.74 13.74,66.04 13.59,65.89 12.57,65.89 12.45,66.01 12.45,66.7 11.96,67.18 11.96,67.82 11.89,67.89 9.83,67.89 9.7,67.77 9.7,67.13 9.63,67.06 9.14,67.06 9.07,67.13 9.07,67.89 8.81,68.15 6.45,68.15 6.12,67.82 6.12,65.89 5.21,65.89
12V on PWR04: 63.75,14.55 63.47,14.27 63.47,8.38 62.56,7.47 30.89,7.47 30.61,7.75 30.61,7.77 28.47,9.91 28.47,17.68 24.13,22.02 19.63,22.02 19.53,22.12 19.53,22.15 7.98,33.71 7.98,46.46 7.32,47.12 7.32,55.65 6.53,56.44 6.53,68.3 7.75,69.52 41.58,69.52 41.83,69.27 41.83,66.88 41.61,66.65 18.34,66.65 12.73,61.04 12.73,41.61 25.93,28.4 30.25,28.4 37.03,21.62 37.03,18.72 37.87,17.88 37.87,17.86 51.69,17.86 52.2,17.35 52.2,13.08 53.04,12.24 59.31,12.24 59.56,12.5 59.56,19.2 60.07,19.71 88.21,19.71 90.47,21.97 90.47,25.86 90.93,26.31 93.9,26.31 94.44,26.85 94.44,34.42 94.97,34.95 118.24,34.95 118.36,34.82 118.36,22.07 117.88,21.59 108.69,21.59 108,20.9 108,17.09 107.65,16.74 104.09,16.74 103.73,16.38 103.73,8.28 103.12,7.67 69.9,7.67 69.72,7.85 69.72,14.05 69.22,14.55
GND on TOP: 148.03,15.8 148.03,18.39 149.49,18.39 149.49,15.8
GND on TOP: 137.16,28.96 144.4,28.96 145.29,28.07 148.21,28.07 148.59,27.69 148.59,9.65 148.34,9.4 135.38,9.4 134.87,8.89 134.87,1.52 134.49,1.14 27.48,1.14 27.48,23.34 28.35,24.21 58.22,24.21 59.05,23.37 59.05,21.72 61.21,19.56 88.9,19.56 91.19,21.84 136.65,21.84 137.29,22.48 137.29,28.45 137.16,28.57 ; 38 cut-outs
GND on TOP: 21.36,66.64 21.11,66.89 21.11,88.1 21.81,88.8 52.18,88.8 52.58,88.4 52.58,84.99 53.14,84.43 105.21,84.43 105.3,84.33 105.3,68.32 105,68.01 94.51,68.01 93.93,67.43 86.93,67.43 86.15,66.64 71.01,66.64 71.01,67.86 70.92,67.86 70.92,66.64 ; 28 cut-outs
GND on TOP: 3,0.51 1.24,1.24 0.51,3 0.51,87 1.24,88.76 3,89.49 147,89.49 148.76,88.76 149.49,87 149.49,40.39 144.07,40.39 144.07,33.53 137.46,33.53 137.46,30.18 149.45,30.18 149.45,30.56 137.85,30.56 137.85,33.2 144.42,33.2 144.42,40.06 149.49,40.06 149.49,17.88 148.46,17.88 148.13,18.21 148.13,27.53 147.83,27.84 144.78,27.84 144.12,28.5 137.03,28.5 136.83,28.7 136.83,37.44 137.74,38.35 137.74,41.15 138.25,41.66 148.13,41.66 148.56,42.09 148.56,65.86 148.18,66.24 143.26,66.24 142.75,66.75 142.75,83.34 141.81,84.28 52.96,84.28 52.4,84.84 52.4,88.39 52.15,88.65 21.82,88.65 21.46,88.29 21.46,66.88 20.88,66.29 20.88,66.27 20.85,66.24 2.46,66.24 1.6,65.38 1.6,44.65 1.17,44.22 1.17,38.76 1.6,38.33 1.6,12.42 1.8,12.22 8.1,12.22 8.1,5.16 8.74,4.52 23.75,4.52 24.08,4.19 24.08,1.73 24.46,1.35 134.59,1.35 134.75,1.5 134.75,8.76 134.76,8.78 134.76,9.56 134.98,9.78 147.96,9.78 147.96,15.98 149.49,15.98 149.49,3 148.76,1.24 147,0.51 ; 6 cut-outs
GND on TOP: 87,20.12 87,21.03 87.17,21.21 88.24,21.21 88.42,21.03 88.42,20.12 88.27,19.96 87.15,19.96
GND on TOP: 61.13,19.41 59.19,21.35 59.19,30.21 62.75,30.21 62.95,30.41 62.95,34.87 64.37,34.87 64.37,35.06 62.95,35.06 62.95,38.27 63.97,39.29 69.12,39.29 70.59,37.82 94.42,37.82 95.05,38.45 95.05,51.01 95.48,51.45 106.86,51.45 107.68,52.27 113.45,52.27 117.4,56.22 117.4,63.84 115.26,65.99 115.26,72.97 113.95,74.27 106.1,74.27 105.5,74.87 105.5,84.41 105.73,84.65 141.79,84.65 142.97,83.47 142.97,66.79 143.38,66.38 143.38,66.39 148.14,66.39 148.64,65.89 148.64,41.98 148.07,41.41 138.37,41.41 137.98,41.02 137.98,38.3 137.27,37.59 137.27,28.69 137.79,28.16 137.79,25.15 137.76,25.15 137.46,24.84 137.46,22.39 136.66,21.6 121.77,21.6 121.77,23.37 120.98,23.37 120.98,21.6 91.26,21.6 89.08,19.41 ; 58 cut-outs
GND on TOP: 23.95,0.91 23.6,1.27 23.6,3.76 23.19,4.17 8.53,4.17 7.82,4.88 7.82,9.96 7.85,9.98 7.85,11.56 7.57,11.84 1.83,11.84 1.42,12.24 1.42,65.48 2.46,66.52 2.46,66.55 20.85,66.55 21.18,66.88 24.33,66.88 24.33,66.3 24.38,66.3 24.38,66.88 55.09,66.88 56.01,65.96 56.01,53.21 53.72,50.93 53.72,23.32 53.16,22.76 28.17,22.76 27.58,22.17 27.58,1.24 27.28,0.94 26.39,0.94 26.37,0.91 ; 28 cut-outs
GND on TOP: 53.64,23.7 53.4,23.94 53.4,50.39 56.27,53.26 56.27,64.38 58.76,66.87 70.92,66.87 70.92,66.57 71,66.57 71,66.87 93.81,66.87 94.9,67.97 104.36,67.97 105.48,69.09 105.48,74.87 105.93,74.87 106.33,74.47 114.24,74.47 115.45,73.26 115.45,66.16 117.52,64.1 117.52,55.94 113.54,51.97 107.61,51.97 106.92,51.27 95.72,51.27 95.31,50.86 95.31,38.27 94.61,37.58 70.58,37.58 69.12,39.03 58.59,39.03 58.12,38.56 58.12,23.95 57.86,23.7 ; 43 cut-outs
GND on BOTTOM: 22.76,16.08 22.78,16.05 22.78,14.24 39.55,14.24 40.41,13.39 40.41,9.35 41.64,8.12 41.64,7.89 41.45,7.71 37.12,7.71 37.13,7.72 37.13,10.69 36.97,10.86 35.97,10.86 35.7,10.59 35.7,10.49 35.23,10.02 35.23,10.03 34.87,9.68 6.27,9.68 5.77,9.17 3.1,9.17 2.39,9.88 2.39,22.02 5.94,22.02 6.2,21.77 6.2,16.08
GND on BOTTOM: 18.38,51.48 21.21,51.48 23.51,49.17 23.51,44.63 22.71,43.84 22.71,30.03 23.82,30.03 23.99,29.86 23.99,28.54 24.39,28.14 26.45,28.14 26.46,28.13 29.68,28.13 29.82,27.99 29.82,22.63 27.68,20.49 23.49,20.49 23.39,20.4 23.39,19.35 23.14,19.1 21.41,19.1 20.99,19.52 20.99,41.52 17.94,44.58 17.94,50.08 18.39,50.54 18.39,51.47
GND on BOTTOM: 12.12,44.32 12.62,43.81 15.47,43.81 19.23,40.06 19.23,18.49 19.7,18.02 19.7,17.2 19.44,16.94 15.01,16.94 14.99,16.97 14.2,16.97 12.85,15.62 8.84,15.62 7.34,17.12 7.34,18.97 9.32,18.97 9.35,18.95 11.84,18.95 12.24,19.35 13.72,19.35 15.01,20.65 15.01,23.55 15.34,23.88 15.34,24.66 15.14,24.87 14.05,24.87 13.46,24.28 13.46,21.13 12.88,20.55 7.32,20.55 5.99,21.87 2.29,21.87 2.29,39.34 1.57,40.06 1.57,41.63 2.49,42.55 4.65,42.55 6.4,44.3 9.98,44.3 10.01,44.32 ; 1 cut-out
GND on BOTTOM: 93.01,66.47 92.66,66.83 92.66,67.36 92.35,67.67 89.71,67.67 89.55,67.83 89.55,76.4 90.4,76.4 91.36,77.37 91.36,82.32 94.21,85.17 103.81,85.17 104.34,84.63 104.34,74.6 109.7,69.24 109.7,60.17 113.16,56.72 128.65,56.72 129.29,56.08 129.49,56.08 129.59,56.18 129.59,57.4 129.72,57.53 130.35,57.53 130.45,57.43 130.45,51.77 130.23,51.54 130.2,51.54 129.82,51.16 129.82,49.17 129.22,48.58 110.86,48.58 110.62,48.82 103.28,48.82 102.64,48.18 78.79,48.18 78.46,48.51 77.72,48.51 77.67,48.46 75.56,48.46 75.36,48.67 75.36,54.48 72.44,57.4 72.44,58.37 73.13,58.37 77.67,62.92 90.93,62.92 92.02,64.01 95.99,64.01 96.22,64.24 96.22,65.07 94.82,66.47 ; 14 cut-outs
GND on BOTTOM: 37.92,63.22 43,63.22 44.12,62.1 44.12,61.29 43.59,60.76 37.82,60.76 37.62,60.96 37.62,62.92 ; 1 cut-out
GND on BOTTOM: 111.1,70.05 111.1,60.6 114.57,57.13 123.45,57.13 125.56,59.25 126.76,59.25 126.96,59.05 126.96,57.27 127.18,57.05 130.38,57.05 130.4,57.07 130.4,62.2 128.04,64.57 128.04,66.04 129.16,66.04 129.31,66.19 129.31,66.34 129.13,66.52 129.13,68.46 129.31,68.63 138.97,68.63 142.33,71.99 142.33,77.03 141.81,77.55 125.72,77.55 125.12,78.15 125.12,82.09 124.2,83.02 108.47,83.02 107.21,84.28 105.77,84.28 105.77,75.39
GND on BOTTOM: 78.95,82.66 85.11,82.66 85.56,82.21 85.56,79.49 85.35,79.28 78.87,79.28 78.51,79.64 78.51,82.22
GND on BOTTOM: 80.67,31.9 84.12,31.9 84.2,31.83 84.2,30.78 84.12,30.71 80.67,30.71 80.59,30.78 80.59,31.83
GND on BOTTOM: 58.84,82.59 65,82.59 65.31,82.27 65.31,79.78 64.81,79.28 59.02,79.28 58.57,79.74 58.57,82.32
GND on BOTTOM: 1.73,50.24 6.6,50.24 7.32,49.53 7.32,45.57 5.54,43.79 1.83,43.79 1.73,43.89 ; 1 cut-out
GND on BOTTOM: 43.34,20.18 47.05,20.18 47.27,19.96 47.27,10.71 47.1,10.54 44.44,10.54 43.63,11.34 43.63,15.27 43.06,15.84 43.06,19.9
GND on BOTTOM: outline of 113 points within 0.51,0.51 149.49,89.49 ; 25 cut-outs
GND on BOTTOM: 113.77,38.92 116.95,38.92 121.01,42.99 126.59,42.99 126.81,42.76 126.81,31.13 126.8,31.11 126.8,29.57 124.51,27.28 117.65,27.28 116.97,26.59 114.55,26.59 114.55,28.57 114.94,28.96 114.94,29.97 114.72,30.19 113.9,30.19 113.9,30.2 113.31,30.78 113.31,38.47
GND on BOTTOM: 131.57,48.34 140.49,48.34 143.46,51.31 143.46,61.9 144.22,62.66 148.36,62.66 148.36,76.38 147.62,77.11 142.24,77.11 142.24,72.95 138.86,69.57 138.86,69.52 138.2,68.86 129.34,68.86 129.08,68.61 129.08,66.24 129.24,66.09 133.48,66.09 133.96,65.61 131.55,63.2 131.55,48.36
GND on BOTTOM: 9.35,50.72 9.35,52.91 9.53,53.09 11.58,53.09 11.79,52.88 11.79,50.52 9.55,50.52
GND on BOTTOM: 30.68,66.45 29.26,67.87 29.26,67.94 32.49,67.94 32.49,68.15 29.26,68.15 29.26,71.02 30.56,71.02 30.56,70.31 30.86,70.31 30.86,71.02 32.56,71.02 32.56,72.01 29.24,72.01 29.24,71.88 21.34,71.88 21.11,72.11 21.11,73.79 21.31,73.99 35.1,73.99 36.27,75.16 36.27,75.74 36.93,76.4 41.17,76.4 42.44,75.13 42.44,67.69 41.2,66.45 33.22,66.45 33.22,67.44 33.02,67.44 33.02,66.45 ; 1 cut-out
GND on BOTTOM: 22.4,55.45 21.46,55.45 20.88,56.03 20.88,60.63 21.11,60.86 22.15,60.86 22.43,60.58 22.43,55.47 ; 1 cut-out
GND on BOTTOM: 64.44,31.9 67.89,31.9 67.97,31.83 67.97,30.78 67.89,30.71 64.44,30.71 64.36,30.78 64.36,31.83
GND on BOTTOM: 148.31,11.46 148.31,13.74 149.49,13.74 149.49,11.46
GND on BOTTOM: outline of 126 points within 54.79,34.98 110.64,76.86 ; 7 cut-outs
GND on BOTTOM: 52.9,63.98 57.99,63.98 58.39,63.58 58.39,62.46 57.78,61.85 57.78,61.85 57.78,60.72 57.76,60.7 57.76,36.4 62.59,31.57 62.59,27.38 62.74,27.23 71.07,27.23 71.08,27.22 75.3,27.22 75.82,26.7 75.82,26.66 76.4,26.08 88.52,26.08 89.79,27.35 98.52,27.35 99.44,26.43 108.94,26.43 110.14,25.23 115.81,25.23 116.08,25.5 121.82,25.5 122.3,25.98 124.97,25.98 127.66,28.68 135.08,28.68 135.23,28.52 135.23,27.38 135.99,26.62 136.93,26.62 138.07,25.48 139.37,25.48 141.19,23.66 146.47,23.66 147.04,23.1 147.04,9.16 146.62,8.75 110.28,8.75 109.32,9.7 89.1,9.7 88.82,9.98 88.82,13.89 86.89,15.82 85.19,15.82 85.17,15.8 75.31,15.8 73.58,14.07 67.06,14.07 65.25,15.88 62.15,15.88 61.34,16.69 59.79,16.69 52.93,23.55 52.93,25.78 49.48,29.24 49.48,31.5 49.7,31.71 50.8,31.71 51.04,31.47 51.05,31.47 51.08,31.45 51.08,29.62 61.34,19.35 69.27,19.35 69.82,19.91 68.48,21.26 61.19,21.26 52.55,29.9 52.55,59.96 51.43,61.09 51.43,62.51 ; 18 cut-outs
GND on BOTTOM: 16.13,53.42 19.86,53.42 20.5,54.05 30.76,54.05 30.76,30.15 30.45,29.84 23.24,29.84 23.06,30.02 23.06,43.87 23.83,44.63 23.83,49.56 21.64,51.74 16.76,51.74 16.13,52.37
GND on GND02: 3,0.51 1.24,1.24 0.51,3 0.51,87 1.24,88.76 3,89.49 147,89.49 148.76,88.76 149.49,87 149.49,3 148.76,1.24 147,0.51 ; 1 cut-out
GND on ART03: 85.5,19.68 85.5,25.7 84.86,26.34 80.44,26.34 80.06,26.72 80.06,29.64 80.07,29.65 80.07,34.28 78.77,35.59 76.25,35.59 75.46,36.37 75.46,49.02 97.38,49.02 97.79,48.62 97.79,21.89 95.58,19.68 ; 1 cut-out
GND on ART03: outline of 87 points within 1.09,1.07 76.07,63.93 ; 16 cut-outs
GND on ART03: outline of 134 points within 11.73,17.81 147.37,83.67 ; 14 cut-outs
GND on ART03: 5.94,42.21 5.94,39.12 6.32,39.12 6.32,39.47 6.63,39.78 6.63,39.95 8.08,41.4 8.69,41.4 8.69,42.21
GND on ART03: 5.18,47.62 5.69,47.62 9.68,51.61 9.68,53.14 9.91,53.37 11.18,53.37 11.43,53.11 11.43,51.69 11.07,51.33 11.07,45.26 10.44,44.63 5.23,44.63 4.88,44.98 4.88,47.32
GND on ART03: 24.46,19.35 24.43,19.38 24.43,30.28 27.43,33.27 31.17,33.27 34.42,36.53 37.06,36.53 38.25,35.33 59.74,35.33 60.22,35.81 78.79,35.81 80.19,34.42 80.19,26.97 80.62,26.54 85.04,26.54 85.75,25.83 85.75,19.61 85.5,19.35 58.86,19.35 58.86,20.16 58.65,20.16 58.65,19.35 ; 17 cut-outs
GND on ART03: 147.7,23.55 147.7,26.95 149.49,26.95 149.49,23.55
GND on ART03: 3,0.51 1.24,1.24 0.51,3 0.51,87 1.24,88.76 3,89.49 147,89.49 148.76,88.76 149.49,87 149.49,26.29 147.85,26.29 147.88,26.31 147.88,27.97 146.28,29.57 137.41,29.57 136.45,30.53 136.45,32.44 134.65,34.24 134.65,42.19 134.2,42.63 132.98,42.63 116.31,59.31 101.98,59.31 89.31,71.98 55.96,71.98 51.28,76.66 51.28,82.27 52.1,83.08 52.1,87.07 50.39,88.77 36.88,88.77 34.7,86.59 34.7,81.97 33.2,80.47 26.9,80.47 26.47,80.9 20.52,80.9 19.86,81.56 18.11,81.56 17.07,80.52 17.07,74.17 17.02,74.12 3.38,74.12 3.07,73.81 3.07,72.54 3.35,72.26 8.18,72.26 8.39,72.05 8.39,52.39 5.71,49.71 1.93,49.71 1.32,49.1 1.32,10.85 3.71,8.46 11.35,8.46 12.06,7.75 12.06,2.82 13.54,1.35 133.81,1.35 135.61,3.15 135.64,3.15 135.92,3.43 141.55,3.43 142.11,3.99 142.11,13.74 141.5,14.35 141.5,15.62 141.66,15.77 147.19,15.77 147.24,15.82 147.24,15.85 147.93,16.54 147.93,24.38 149.49,24.38 149.49,3 148.76,1.24 147,0.51 ; 3 cut-outs
GND on ART03: 103,16 103.68,15.32 103.68,7.16 103.15,6.63 73.33,6.63 67.82,12.14 60.48,12.14 60.02,12.6 60.02,15.65 60.38,16
GND on PWR04: 36.22,56.49 76.12,56.49 76.58,56.03 76.58,51.13 76.96,50.75 79.76,50.75 80.26,51.26 80.26,56.26 80.49,56.49 107.87,56.49 108.25,56.11 108.25,52.86 108.79,52.32 116.33,52.32 116.56,52.1 116.56,38.18 116.36,37.97 113.23,37.97 113.08,38.13 113.08,39.24 112.78,39.55 100.03,39.55 99.77,39.8 99.77,42.62 99.44,42.95 98.37,42.95 98.15,43.18 98.15,44.78 97.69,45.24 36.42,45.24 35.92,45.75 35.92,56.18
GND on PWR04: 148.46,25.2 148.46,29.01 149.49,29.01 149.49,25.2
GND on PWR04: 131.6,76.91 131.6,67.64 130.91,66.95 103.66,66.95 103.56,67.06 103.56,76.66 104.11,77.22 131.29,77.22
GND on PWR04: 3,0.51 1.24,1.24 0.51,3 0.51,87 1.24,88.76 3,89.49 147,89.49 148.76,88.76 149.49,87 149.49,28.52 148.62,28.52 148.62,29.51 148.01,30.12 138.51,30.12 136.55,32.08 136.55,55.6 142.57,61.62 142.57,87.66 141.6,88.62 92.25,88.62 91.62,87.99 91.62,71.58 91.11,71.07 83.59,71.07 83.06,70.54 83.06,66.93 82.73,66.6 53.64,66.6 53.09,67.16 53.09,67.18 52.86,67.41 52.86,85.6 52.48,85.98 33.63,85.98 33.3,85.65 33.3,78.28 32.74,77.72 3.89,77.72 3.53,77.37 3.53,75.11 3.19,74.76 2.17,74.76 1.07,73.66 1.07,12.47 12.27,1.27 141.58,1.27 142.21,1.91 142.21,6.17 143.54,7.49 148.16,7.49 148.82,8.15 148.82,26.19 149.49,26.19 149.49,3 148.76,1.24 147,0.51
GND on GND05: 3,0.51 1.24,1.24 0.51,3 0.51,87 1.24,88.76 3,89.49 147,89.49 148.76,88.76 149.49,87 149.49,3 148.76,1.24 147,0.51
VBUS5V0_TYPEC on BOTTOM: 26.19,81.38 26.19,80.14 26.97,79.35 27.91,79.35 28.12,79.15 28.12,76.91 28.4,76.63 30.56,76.63 30.91,76.99 30.91,77.6 30.84,77.67 29.06,77.67 28.83,77.9 28.83,79.38 29.72,80.26 29.72,81.97 29.34,82.35 29.13,82.35 28.98,82.19 28.98,80.77 28.73,80.52 27.13,80.52 26.85,80.8 26.85,81.41 26.72,81.53 26.34,81.53
VBUS5V0_TYPEC on PWR04: 26.11,86.06 26.11,80.52 26.37,80.26 29.31,80.26 29.57,80.52 29.57,85.95 30.3,86.69 30.3,87.3 29.93,87.67 25.77,87.67 25.58,87.48 25.58,86.59
VCC5V0_SYS_S5 on TOP: 16.36,64.8 16.36,60.73 16.08,60.45 16.08,52.53 15.8,52.25 14.81,52.25 14.63,52.43 14.63,54.53 14.27,54.89 14.27,60.68 14.53,60.93 14.53,64.8
VCC5V0_SYS_S5 on BOTTOM: 13.18,58.85 13.18,55.96 12.8,55.58 12.14,55.58 12.09,55.52 12.09,54.97 12.14,54.91 12.98,54.91 14.15,53.75 14.15,52.53 14.4,52.27 15.77,52.27 15.88,52.37 15.88,53.33 16.02,53.47 16.02,53.74 15.88,53.88 15.88,54.48 15.71,54.65 15.2,54.65 14.81,55.04 14.81,56.72 15.52,57.43 15.52,58.85
VCC5V0_USB20_HOST on BOTTOM: 133.22,86.11 131.98,86.11 131.98,84.79 132.18,84.58 132.77,84.58 132.92,84.43 132.92,80.29 133.3,79.91 135.64,79.91 136.22,79.32 136.22,77.7 136.55,77.37 137.85,77.37 137.85,77.39 138.36,77.9 138.36,81.41 137.95,81.81 135.15,81.81 134.67,82.3 134.67,84.3 133.22,85.75
VCC5V0_USB30_HOST on BOTTOM: 112.8,86.11 112.8,84.89 113.08,84.61 113.51,84.61 113.69,84.43 113.69,82.09 113.92,81.86 116.81,81.86 117.12,81.56 117.12,80.06 117.37,79.81 118.62,79.81 118.85,80.04 118.85,82.91 118.39,83.36 115.7,83.36 115.49,83.57 115.49,85.04 115.27,85.27 114.35,85.27 114.02,85.6 114.02,86.11
VCC_1V8_S3 on TOP: 19.79,59.94 19.79,57.51 20.24,57.05 20.24,54.36 19.79,53.9 19.79,51.99 19.86,51.92 20.5,51.92 20.6,52.02 20.6,59.84 20.85,60.1 20.85,64.8 20.83,64.82 20.07,64.82 20.04,64.8 20.04,60.2
VCC_1V8_S3 on TOP: 92.04,27.32 93.14,27.32 93.29,27.17 93.29,26.72 93.17,26.59 92.79,26.59 92.65,26.73 92.04,26.73 91.91,26.86 91.91,27.19
VCC_1V8_S3 on PWR04: 20.14,54.13 20.14,51.84 35.86,36.12 75.84,36.12 76.81,35.15 89.26,35.15 90.47,33.93 90.47,26.92 90.73,26.67 93.75,26.67 94.11,27.03 94.11,40.31 92.96,41.45 36.09,41.45 23.24,54.31 20.32,54.31
VCC_3V3_S0 on TOP: 8.56,45.06 8.66,44.96 9.6,44.96 9.75,45.11 9.75,46.25 9.93,46.43 13.08,46.43 13.92,45.59 15.57,45.59 15.72,45.75 15.72,45.95 14,47.68 8.66,47.68 8.56,47.57
VCC_3V3_S0 on TOP: 17.78,60.22 17.78,51.99 17.86,51.92 18.52,51.92 18.59,51.99 18.59,60.12 18.85,60.38 18.85,64.8 18.82,64.82 18.06,64.82 18.03,64.8 18.03,60.48
VCC_3V3_S0 on ART03: 13.72,45.77 13.72,50.29 14.1,50.67 14.1,53.62 15.14,54.66 18.72,54.66 18.95,54.43 18.95,52.17 18.72,51.94 17.88,51.94 15.7,49.76 15.7,45.75 15.52,45.57 13.92,45.57
VCC_3V3_S0 on PWR04: 19.91,52.1 19.91,54.23 20.22,54.53 23.14,54.53 23.15,54.52 23.43,54.52 36.02,41.94 93.07,41.94 94.54,40.46 94.54,35.74 95.02,35.26 124.18,35.26 124.71,34.72 124.71,20.5 124.99,20.22 126.7,20.22 127.03,20.55 127.03,37.01 126.34,37.69 98.4,37.69 97.87,38.23 97.87,44.48 97.46,44.88 38.13,44.88 26.54,56.46 18.72,56.46 18.25,55.99 18.25,51.98 18.31,51.92 19.74,51.92
